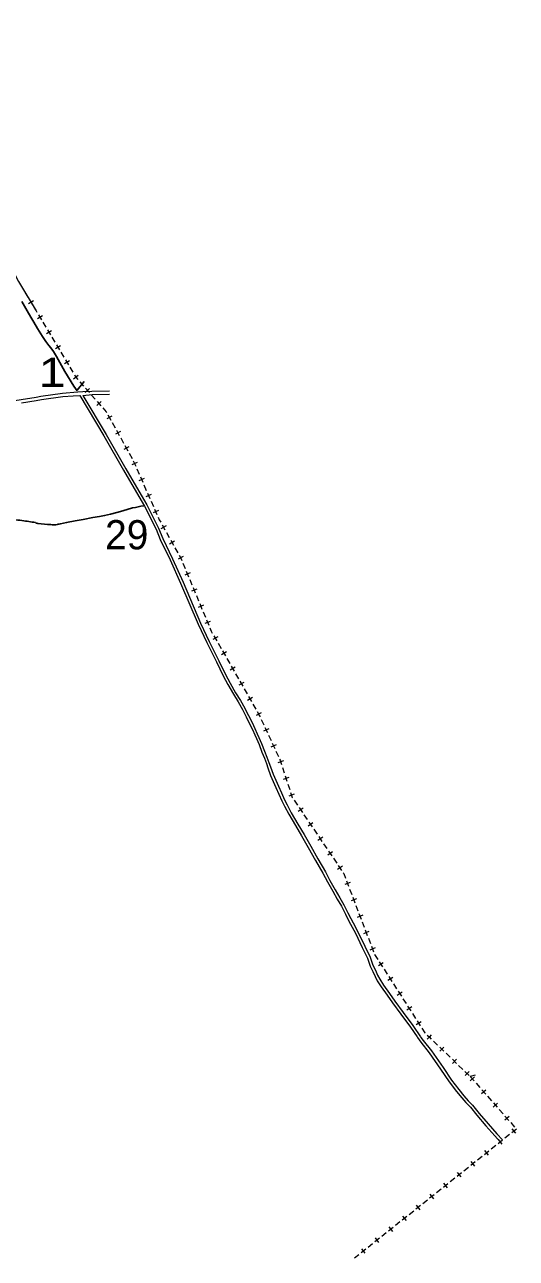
# Model space of a CAD drawing. Extents: x 476989 to 498418, y 4381813 to 4416555.
# Drawn here: x 487660 to 488503, y 4383749 to 4385862 of the extents above; entities that cross this region are included whole.
import ezdxf

# ---------------------------------------------------------------- set-up
doc = ezdxf.new("R2010")
doc.units = 0
doc.header["$LTSCALE"] = 20
for name, color, linetype, lineweight in [('13', 7, 'Continuous', 13), ('34', 7, 'Continuous', 13), ('36', 7, 'Continuous', 13), ('6', 7, 'Continuous', 25)]:
    doc.layers.add(name, color=color, linetype=linetype, lineweight=lineweight)

msp = doc.modelspace()

# ---------------------------------------------------------------- linework, layer by layer
at = {"layer": '34'}
for p, q in [((487660.88, 4385403.79), (487666.01, 4385395.21)), ((487675.43, 4385389.2), (487666.84, 4385384.07)), ((487668.57, 4385390.93), (487673.7, 4385382.34)), ((487676.26, 4385378.05), (487680.1, 4385371.63)), ((487680.1, 4385371.63), (487681.39, 4385369.47)), ((487690.81, 4385363.45), (487682.22, 4385358.33)), ((487683.95, 4385365.18), (487689.08, 4385356.6)), ((487691.65, 4385352.31), (487696.78, 4385343.72)), ((487706.19, 4385337.71), (487697.61, 4385332.58)), ((487699.34, 4385339.44), (487704.47, 4385330.85)), ((487707.03, 4385326.56), (487712.16, 4385317.98)), ((487721.58, 4385311.97), (487712.99, 4385306.84)), ((487714.72, 4385313.69), (487719.85, 4385305.11)), ((487722.41, 4385300.82), (487727.54, 4385292.23)), ((487730.1, 4385287.95), (487735.23, 4385279.37)), ((487736.96, 4385286.22), (487728.38, 4385281.09)), ((487737.8, 4385275.07), (487742.93, 4385266.49)), ((487751.82, 4385261.23), (487744.31, 4385254.62)), ((487754.68, 4385250.42), (487761.29, 4385242.92)), ((487771.65, 4385238.73), (487764.14, 4385232.12)), ((487764.59, 4385239.18), (487771.2, 4385231.68)), ((487774.51, 4385227.92), (487781.12, 4385220.42)), ((487791.48, 4385216.23), (487783.97, 4385209.62)), ((487784.42, 4385216.68), (487791.03, 4385209.18)), ((487809.92, 4385191.44), (487801.18, 4385186.58)), ((487803.12, 4385193.38), (487807.98, 4385184.64)), ((487810.4, 4385180.27), (487815.26, 4385171.53)), ((487824.48, 4385165.23), (487815.74, 4385160.37)), ((487817.68, 4385167.17), (487822.54, 4385158.43)), ((487824.97, 4385154.06), (487829.83, 4385145.31)), ((487832.25, 4385140.95), (487837.11, 4385132.21)), ((487839.05, 4385139.01), (487830.31, 4385134.15)), ((487839.53, 4385127.84), (487844.39, 4385119.1)), ((487853.11, 4385112.03), (487843.96, 4385107.99)), ((487846.51, 4385114.59), (487850.56, 4385105.44)), ((487852.58, 4385100.87), (487856.62, 4385091.72)), ((487865.24, 4385084.61), (487856.09, 4385080.56)), ((487858.64, 4385087.16), (487862.69, 4385078.01)), ((487864.71, 4385073.44), (487868.75, 4385064.29)), ((487877.37, 4385057.18), (487868.22, 4385053.14)), ((487870.77, 4385059.73), (487874.82, 4385050.59)), ((487876.84, 4385046.01), (487880.89, 4385036.87)), ((487889.5, 4385029.75), (487880.35, 4385025.71)), ((487882.9, 4385032.3), (487886.95, 4385023.16)), ((487902.68, 4385003.38), (487893.96, 4384998.49)), ((487895.88, 4385005.3), (487900.77, 4384996.58)), ((487903.21, 4384992.21), (487908.1, 4384983.49)), ((487917.35, 4384977.22), (487908.63, 4384972.33)), ((487910.54, 4384979.14), (487915.43, 4384970.42)), ((487917.88, 4384966.06), (487922.77, 4384957.33)), ((487932.01, 4384951.06), (487923.29, 4384946.17)), ((487931.57, 4384939.42), (487935.41, 4384930.19)), ((487943.86, 4384922.89), (487934.63, 4384919.04)), ((487937.33, 4384925.58), (487941.17, 4384916.35)), ((487943.09, 4384911.73), (487946.93, 4384902.5)), ((487955.38, 4384895.2), (487946.15, 4384891.35)), ((487948.85, 4384897.89), (487952.69, 4384888.66)), ((487954.61, 4384884.04), (487958.45, 4384874.81)), ((487966.9, 4384867.51), (487957.67, 4384863.66)), ((487960.36, 4384870.2), (487964.2, 4384860.97)), ((487966.13, 4384856.35), (487969.97, 4384847.12)), ((487978.42, 4384839.82), (487969.19, 4384835.98)), ((487971.88, 4384842.51), (487975.72, 4384833.28)), ((487991.22, 4384813.46), (487982.54, 4384808.49)), ((487984.4, 4384815.31), (487989.37, 4384806.63)), ((487991.85, 4384802.3), (487996.82, 4384793.62)), ((488006.12, 4384787.43), (487997.44, 4384782.46)), ((487999.3, 4384789.29), (488004.27, 4384780.61)), ((488006.75, 4384776.27), (488011.72, 4384767.59)), ((488021.02, 4384761.4), (488012.34, 4384756.44)), ((488014.2, 4384763.26), (488019.16, 4384754.58)), ((488021.65, 4384750.24), (488026.62, 4384741.56)), ((488035.92, 4384735.38), (488027.24, 4384730.41)), ((488029.1, 4384737.23), (488034.06, 4384728.55)), ((488036.55, 4384724.21), (488041.52, 4384715.53)), ((488050.82, 4384709.35), (488042.14, 4384704.38)), ((488043.99, 4384711.2), (488048.96, 4384702.52)), ((488051.45, 4384698.19), (488056.41, 4384689.51)), ((488065.72, 4384683.32), (488057.04, 4384678.35)), ((488065.82, 4384671.89), (488070, 4384662.8)), ((488078.72, 4384655.82), (488069.64, 4384651.64)), ((488072.09, 4384658.27), (488076.27, 4384649.19)), ((488078.36, 4384644.65), (488082.54, 4384635.56)), ((488091.26, 4384628.58), (488082.18, 4384624.4)), ((488084.63, 4384631.03), (488088.81, 4384621.95)), ((488090.91, 4384617.4), (488095.09, 4384608.32)), ((488103.7, 4384600.68), (488094.19, 4384597.56)), ((488102.06, 4384589.62), (488105.18, 4384580.12)), ((488113.05, 4384572.18), (488103.54, 4384569.07)), ((488106.74, 4384575.38), (488109.85, 4384565.88)), ((488111.41, 4384561.12), (488114.53, 4384551.62)), ((488122.4, 4384543.69), (488112.89, 4384540.57)), ((488122.17, 4384533.32), (488127.77, 4384525.04)), ((488137.51, 4384519.57), (488129.23, 4384513.96)), ((488130.57, 4384520.91), (488136.18, 4384512.62)), ((488138.98, 4384508.48), (488144.59, 4384500.2)), ((488154.33, 4384494.73), (488146.05, 4384489.13)), ((488147.38, 4384496.07), (488152.99, 4384487.79)), ((488155.79, 4384483.65), (488161.4, 4384475.37)), ((488171.14, 4384469.9), (488162.86, 4384464.29)), ((488164.19, 4384471.24), (488169.8, 4384462.95)), ((488172.6, 4384458.81), (488178.21, 4384450.53)), ((488187.95, 4384445.06), (488179.67, 4384439.46)), ((488181.01, 4384446.4), (488186.61, 4384438.12)), ((488189.41, 4384433.98), (488195.02, 4384425.7)), ((488197.82, 4384421.57), (488203.42, 4384413.28)), ((488204.76, 4384420.23), (488196.48, 4384414.62)), ((488218.3, 4384392.39), (488208.96, 4384388.83)), ((488211.85, 4384395.28), (488215.41, 4384385.94)), ((488217.19, 4384381.27), (488220.76, 4384371.92)), ((488228.99, 4384364.37), (488219.64, 4384360.81)), ((488222.53, 4384367.26), (488226.1, 4384357.92)), ((488227.88, 4384353.25), (488231.44, 4384343.9)), ((488239.67, 4384336.35), (488230.33, 4384332.79)), ((488233.22, 4384339.24), (488236.78, 4384329.9)), ((488238.56, 4384325.22), (488242.12, 4384315.88)), ((488250.36, 4384308.33), (488241.01, 4384304.76)), ((488243.9, 4384311.22), (488247.47, 4384301.87)), ((488249.25, 4384297.2), (488252.81, 4384287.86)), ((488261.04, 4384280.31), (488251.7, 4384276.74)), ((488254.59, 4384283.2), (488258.15, 4384273.85)), ((488274.9, 4384255.04), (488266.48, 4384249.64)), ((488267.99, 4384256.55), (488273.39, 4384248.13)), ((488276.09, 4384243.92), (488281.5, 4384235.51)), ((488284.19, 4384231.31), (488289.59, 4384222.89)), ((488291.1, 4384229.8), (488282.68, 4384224.4)), ((488292.29, 4384218.68), (488297.69, 4384210.27)), ((488307.3, 4384204.56), (488298.88, 4384199.16)), ((488300.39, 4384206.07), (488305.79, 4384197.65)), ((488308.49, 4384193.44), (488313.89, 4384185.03)), ((488323.5, 4384179.32), (488315.08, 4384173.92)), ((488316.59, 4384180.83), (488321.99, 4384172.41)), ((488324.69, 4384168.21), (488330.09, 4384159.79)), ((488339.69, 4384154.08), (488331.28, 4384148.68)), ((488332.79, 4384155.59), (488338.19, 4384147.17)), ((488349.98, 4384131.17), (488353.26, 4384128.02)), ((488353.89, 4384128.02), (488350.12, 4384124.1)), ((488353.26, 4384128.02), (488357.19, 4384124.24)), ((488357.05, 4384131.31), (488353.89, 4384128.02)), ((488360.79, 4384120.77), (488368, 4384113.84)), ((488371.6, 4384110.38), (488378.81, 4384103.45)), ((488378.67, 4384110.52), (488371.74, 4384103.32)), ((488382.41, 4384099.99), (488389.62, 4384093.06)), ((488393.22, 4384089.6), (488400.43, 4384082.67)), ((488400.29, 4384089.74), (488393.36, 4384082.53)), ((488404.03, 4384079.2), (488411.24, 4384072.27)), ((488414.84, 4384068.81), (488422.04, 4384061.88)), ((488421.9, 4384068.95), (488414.97, 4384061.74)), ((488432.07, 4384062.39), (488424, 4384060)), ((488431.05, 4384059.55), (488423.53, 4384052.95)), ((488424, 4384060), (488430.59, 4384052.49)), ((488433.89, 4384048.73), (488440.49, 4384041.22)), ((488450.83, 4384037.01), (488443.32, 4384030.41)), ((488443.78, 4384037.47), (488450.37, 4384029.95)), ((488453.67, 4384026.2), (488460.27, 4384018.68)), ((488470.62, 4384014.47), (488463.1, 4384007.87)), ((488463.56, 4384014.93), (488470.16, 4384007.41)), ((488473.46, 4384003.66), (488480.05, 4383996.14)), ((488490.4, 4383991.93), (488482.89, 4383985.34)), ((488483.35, 4383992.39), (488489.94, 4383984.88)), ((488493.24, 4383981.12), (488499.84, 4383973.6)), ((488491.12, 4383960.53), (488483.3, 4383954.3)), ((488502.85, 4383969.88), (488495.03, 4383963.65)), ((488502.05, 4383962.85), (488495.82, 4383970.67)), ((488467.66, 4383941.84), (488459.84, 4383935.61)), ((488479.39, 4383951.19), (488471.57, 4383944.95)), ((488478.6, 4383944.16), (488472.37, 4383951.98)), ((488432.49, 4383913.8), (488424.67, 4383907.57)), ((488431.69, 4383906.78), (488425.46, 4383914.6)), ((488444.21, 4383923.15), (488436.39, 4383916.91)), ((488455.94, 4383932.5), (488448.12, 4383926.26)), ((488455.15, 4383925.47), (488448.91, 4383933.29)), ((488409.04, 4383895.11), (488401.22, 4383888.88)), ((488408.24, 4383888.09), (488402.01, 4383895.91)), ((488420.76, 4383904.46), (488412.94, 4383898.22)), ((488385.58, 4383876.42), (488377.76, 4383870.19)), ((488384.79, 4383869.39), (488378.56, 4383877.21)), ((488397.31, 4383885.76), (488389.48, 4383879.53)), ((488362.13, 4383857.73), (488354.31, 4383851.5)), ((488361.34, 4383850.7), (488355.1, 4383858.52)), ((488373.85, 4383867.07), (488366.03, 4383860.84)), ((488326.95, 4383829.69), (488319.13, 4383823.46)), ((488338.68, 4383839.04), (488330.86, 4383832.81)), ((488337.88, 4383832.01), (488331.65, 4383839.83)), ((488350.4, 4383848.38), (488342.58, 4383842.15)), ((488303.49, 4383811), (488295.67, 4383804.77)), ((488315.22, 4383820.35), (488307.4, 4383814.11)), ((488314.43, 4383813.32), (488308.2, 4383821.14)), ((488280.04, 4383792.31), (488272.22, 4383786.07)), ((488291.77, 4383801.66), (488283.95, 4383795.42)), ((488290.98, 4383794.63), (488284.75, 4383802.45)), ((488256.59, 4383773.62), (488248.77, 4383767.38)), ((488268.32, 4383782.96), (488260.5, 4383776.73)), ((488267.52, 4383775.94), (488261.29, 4383783.76)), ((488233.14, 4383754.92), (488225.32, 4383748.69)), ((488244.87, 4383764.27), (488237.05, 4383758.04)), ((488244.07, 4383757.25), (488237.84, 4383765.07))]:
    msp.add_line(p, q, dxfattribs=at)
for points in [[(487280.6, 4386441.97), (487080, 4386339), (487267, 4386051), (487354, 4385933), (487441, 4385795), (487598, 4385523), (487650, 4385422), (487680.1, 4385371.64)], [(487745.49, 4385262.21), (487748, 4385258), (487751.37, 4385254.17)], [(487794.34, 4385205.43), (487800, 4385199), (487800.7, 4385197.75)], [(487888.97, 4385018.59), (487891, 4385014), (487893.44, 4385009.65)], [(487925.21, 4384952.98), (487928, 4384948), (487929.65, 4384944.04)], [(487977.64, 4384828.66), (487980, 4384823), (487981.92, 4384819.64)], [(488058.89, 4384685.18), (488063, 4384678), (488063.72, 4384676.43)], [(488097.18, 4384603.79), (488098, 4384602), (488100.5, 4384594.37)], [(488116.09, 4384546.88), (488119, 4384538), (488119.37, 4384537.46)], [(488206.23, 4384409.14), (488207, 4384408), (488210.07, 4384399.95)], [(488259.93, 4384269.18), (488260, 4384269), (488265.3, 4384260.75)], [(488340.89, 4384142.97), (488346, 4384135), (488346.38, 4384134.63)]]:
    msp.add_lwpolyline(points, dxfattribs=at)
at = {"layer": '36'}
for p, q in [((487679.81, 4385224.07), (487679.85, 4385224.08)), ((487679.8, 4385218.38), (487679.84, 4385218.39)), ((488332.78, 4384128.05), (488333.4, 4384127.12)), ((488338.74, 4384128.04), (488339.36, 4384127.11))]:
    msp.add_line(p, q, dxfattribs=at)
for points in [[(487497.15, 4385199.42), (487509.69, 4385199.56), (487530.73, 4385201.64), (487543.2, 4385202.51), (487556.97, 4385203.85), (487571.79, 4385206.52), (487597.97, 4385211.35), (487621.23, 4385214.93), (487654.34, 4385219.7), (487679.81, 4385224.07)], [(487679.84, 4385218.39), (487689.06, 4385219.97), (487725.96, 4385225.31), (487743.45, 4385226.24), (487754.77, 4385226.5)], [(487679.85, 4385224.08), (487688.19, 4385225.51), (487725.41, 4385230.89), (487751.05, 4385232.88)], [(487751.51, 4385233.11), (487760.04, 4385233.57), (487775.61, 4385233.93), (487805.83, 4385234.71)], [(487754.77, 4385226.5), (487795.93, 4385157.57), (487829.92, 4385098.83), (487852.21, 4385060.31)], [(487760.04, 4385226.64), (487775.98, 4385228.34), (487805.98, 4385229.09)], [(487760.04, 4385226.64), (487799.89, 4385159.9), (487833.9, 4385101.14), (487856.19, 4385062.62)], [(487655.21, 4385214.16), (487679.8, 4385218.38)], [(487852.21, 4385060.31), (487865.52, 4385037.09), (487871.17, 4385026.06), (487877.83, 4385013.17), (487885.41, 4384997.67), (487892.78, 4384980.04), (487909.58, 4384945.08), (487927.48, 4384905.25), (487957.67, 4384834.81), (487972.51, 4384803.57), (487989.09, 4384770.37), (488000.47, 4384746.72), (488008.53, 4384731.68), (488017.92, 4384715.2), (488026.08, 4384702.24), (488033.4, 4384688.72), (488037.26, 4384681.81), (488039.95, 4384676.45), (488045.87, 4384664.41), (488050.54, 4384654.49), (488054.62, 4384645.57), (488057.39, 4384639.08), (488062.05, 4384628.97), (488066.76, 4384615.91), (488071.16, 4384605.55), (488074.65, 4384596.59), (488077, 4384588.77)], [(487856.19, 4385062.62), (487869.5, 4385039.41), (487875.26, 4385028.16), (487881.94, 4385015.24), (487889.6, 4384999.57), (487896.98, 4384981.93), (487913.76, 4384947.02), (487931.69, 4384907.09), (487961.86, 4384836.7), (487976.64, 4384805.58), (487993.22, 4384772.4), (488004.57, 4384748.81), (488012.55, 4384733.91), (488021.87, 4384717.57), (488030.06, 4384704.56), (488037.43, 4384690.93), (488041.33, 4384683.96), (488044.07, 4384678.49), (488050.02, 4384666.41), (488054.72, 4384656.43), (488058.83, 4384647.43), (488061.6, 4384640.95), (488066.31, 4384630.72), (488071.05, 4384617.59), (488075.42, 4384607.28), (488078.92, 4384598.31), (488081.65, 4384590.5)], [(488081.65, 4384590.5), (488086.37, 4384577.81), (488090.65, 4384567.62), (488095.25, 4384557.47), (488100.6, 4384545.98), (488105.56, 4384534.32), (488109.92, 4384525.64), (488117.24, 4384512.11), (488128.55, 4384492.58), (488139.09, 4384474.89), (488150.57, 4384454.8), (488162.92, 4384432.9), (488175.67, 4384411.04), (488183.45, 4384396.02), (488192.62, 4384379.97), (488200.42, 4384366.3), (488207.44, 4384354.1), (488214.28, 4384340.4), (488219.04, 4384330.9), (488222.99, 4384323.32), (488231.38, 4384308.11), (488243.29, 4384283.17), (488252.18, 4384264.54), (488257.14, 4384250.9), (488261.27, 4384242.16), (488265.21, 4384233.89), (488268.91, 4384226.73), (488275.32, 4384216.42), (488285.7, 4384202.17), (488294.93, 4384189.09), (488309.18, 4384169.66), (488325.75, 4384147.54), (488338.74, 4384128.04)], [(488077, 4384588.77), (488081.75, 4384575.98), (488086.1, 4384565.63), (488090.74, 4384555.4), (488096.06, 4384543.96), (488101.05, 4384532.24), (488105.52, 4384523.34), (488112.91, 4384509.68), (488124.28, 4384490.07), (488134.8, 4384472.39), (488146.25, 4384452.35), (488158.62, 4384430.43), (488171.32, 4384408.65), (488179.09, 4384393.64), (488188.32, 4384377.51), (488196.12, 4384363.84), (488203.07, 4384351.75), (488209.85, 4384338.18), (488214.63, 4384328.65), (488218.61, 4384320.97), (488226.97, 4384305.84), (488238.81, 4384281.03), (488247.6, 4384262.62), (488252.55, 4384248.99), (488256.79, 4384240.03), (488260.77, 4384231.68), (488264.59, 4384224.27), (488271.21, 4384213.65), (488281.67, 4384199.28), (488290.9, 4384186.19), (488305.19, 4384166.71), (488321.7, 4384144.67), (488332.78, 4384128.05)], [(488333.4, 4384127.12), (488338.92, 4384118.84), (488353.38, 4384100.94), (488373.15, 4384072.85), (488387.79, 4384050.88), (488400.24, 4384034.62), (488409.33, 4384023.73), (488416.52, 4384015.35), (488424.19, 4384007.74), (488435.14, 4383993.67), (488450.82, 4383975.8), (488465.89, 4383958.57), (488475.23, 4383948.42)], [(488339.36, 4384127.11), (488342.92, 4384121.78), (488357.34, 4384103.93), (488377.25, 4384075.65), (488391.83, 4384053.77), (488404.12, 4384037.72), (488413.11, 4384026.93), (488420.16, 4384018.74), (488427.91, 4384011.04), (488438.97, 4383996.84), (488454.55, 4383979.06), (488469.58, 4383961.88), (488479.08, 4383951.57)]]:
    msp.add_lwpolyline(points, dxfattribs=at)
at = {"layer": '6'}
msp.add_line((487750.16, 4385235.72), (487762.56, 4385250.47), dxfattribs=at)
for points in [[(487680, 4385345.5), (487666.97, 4385367.8), (487655.53, 4385387.66)], [(487750.13, 4385234.72), (487744.74, 4385242.95), (487729.34, 4385267.75), (487714.67, 4385293.38), (487709.58, 4385302.34), (487705.22, 4385308.13), (487701.54, 4385312.54), (487696.47, 4385319.22), (487690.86, 4385327.71), (487682.31, 4385341.56), (487680.05, 4385345.41)], [(487865.21, 4385037.63), (487859.62, 4385036.92), (487850.2, 4385034.95), (487845.15, 4385034.12), (487835.92, 4385031.69), (487824.31, 4385028.1), (487818.44, 4385026.24), (487807.39, 4385023.47), (487797.39, 4385021.15), (487788.46, 4385019.33), (487777.26, 4385017.69), (487760.7, 4385014.55), (487747, 4385012.27), (487732.17, 4385009.18), (487721.55, 4385007.15), (487719.36, 4385006.58), (487717.38, 4385006.15), (487716.36, 4385005.78), (487715.95, 4385005.62), (487713.55, 4385004.93)]]:
    msp.add_lwpolyline(points, dxfattribs=at)
for points in [[(487503.02, 4385116.48), (487517.08, 4385103.65), (487539.5, 4385086.52), (487549.79, 4385077.07), (487559.41, 4385067.47), (487578.99, 4385051.21), (487590.49, 4385042.04), (487603.03, 4385032.63), (487610.45, 4385026.75), (487614.38, 4385023.32), (487616.24, 4385022.01), (487617.43, 4385021.32), (487619.51, 4385019.87), (487621.29, 4385018.79), (487632.76, 4385015.64), (487641.4, 4385014.37), (487655.73, 4385012.48), (487679.12, 4385009.11)], [(487679.48, 4385008.17), (487682.96, 4385007.7), (487705.29, 4385005.58), (487713.54, 4385005.01)]]:
    msp.add_spline(points, degree=3, dxfattribs=at)

# ---------------------------------------------------------------- texts
at = {"layer": '13', "width": 1.25}
msp.add_text('1', height=50, dxfattribs=at).set_placement((487684.03, 4385241.38))
at = {"layer": '13'}
msp.add_text('29', height=50, dxfattribs=at).set_placement((487798.02, 4384963.25))

doc.saveas('drawing.dxf')
